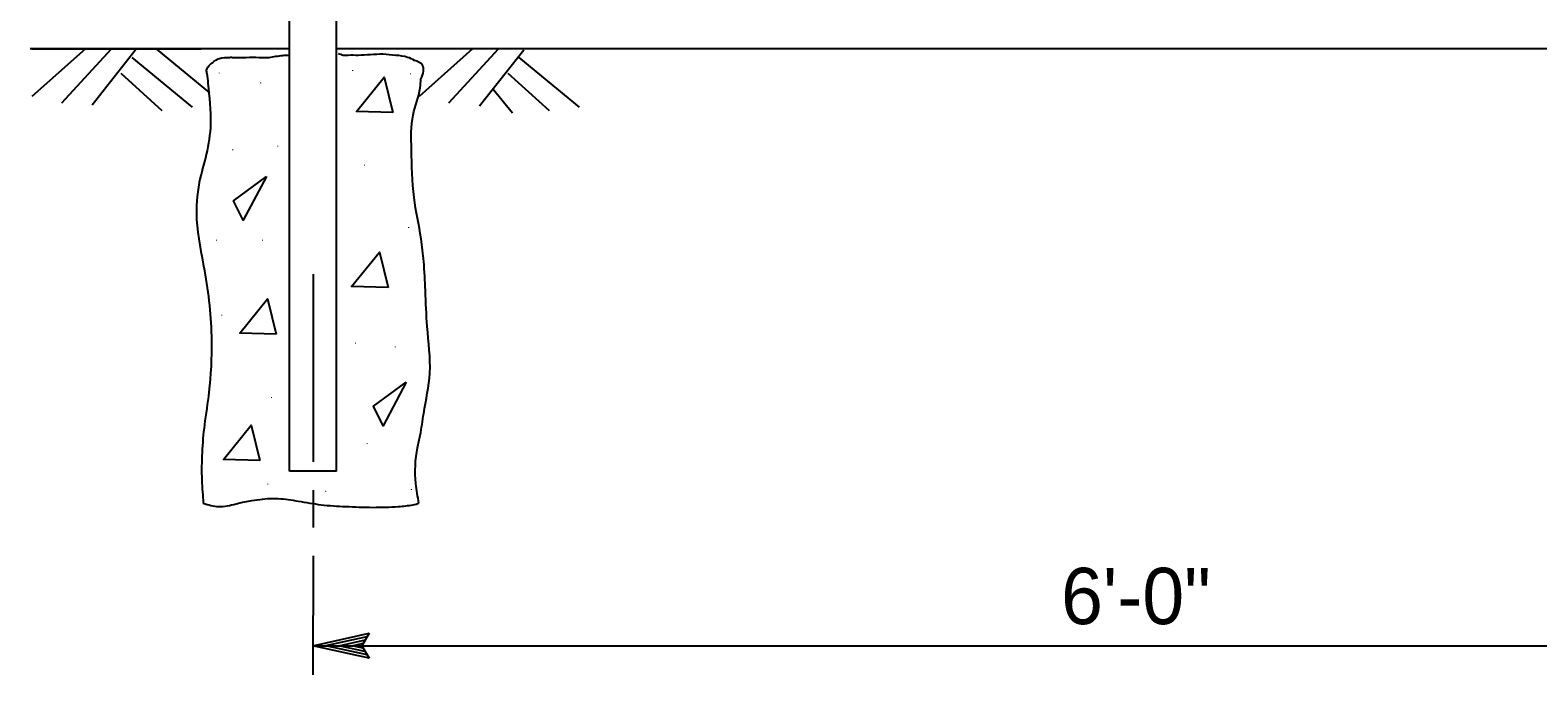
# Model space of a CAD drawing. Extents: x 6710407 to 6714861, y 1868090 to 1871317.
# Drawn here: x 6712140.6 to 6712301.4, y 1870303 to 1870371.8 of the extents above; entities that cross this region are included whole.
import ezdxf

# ---------------------------------------------------------------- set-up
doc = ezdxf.new("R2010")
doc.units = 0
for name, color, linetype in [('G-MARK', 7, 'Continuous'), ('G-TEXT', 7, 'Continuous'), ('Nongeo Data(60)', 7, 'Continuous')]:
    doc.layers.add(name, color=color, linetype=linetype)

msp = doc.modelspace()

# ---------------------------------------------------------------- linework, layer by layer
at = {"layer": 'G-MARK'}
msp.add_line((6712170.79, 1870306.15), (6712345.95, 1870306.15), dxfattribs=at)
for points in [[(6712170.83, 1870345.74), (6712170.81, 1870325.74)], [(6712170.81, 1870322.74), (6712170.81, 1870318.74)], [(6712170.8, 1870315.74), (6712170.79, 1870303.05)]]:
    msp.add_lwpolyline(points, dxfattribs=at)
at = {"layer": 'G-TEXT'}
for p, q in [((6712170.79, 1870306.15), (6712176.79, 1870307.48)), ((6712172.18, 1870306.16), (6712176.56, 1870307.13)), ((6712176.79, 1870307.48), (6712175.99, 1870306.15)), ((6712176.79, 1870307.48), (6712176.79, 1870307.48)), ((6712176.79, 1870304.81), (6712170.79, 1870306.15)), ((6712170.79, 1870306.15), (6712170.79, 1870306.15)), ((6712176.57, 1870305.17), (6712172.17, 1870306.15)), ((6712173.55, 1870306.15), (6712176.38, 1870306.78)), ((6712176.34, 1870305.53), (6712173.55, 1870306.15)), ((6712174.93, 1870306.15), (6712176.14, 1870306.42)), ((6712176.16, 1870305.88), (6712174.93, 1870306.15)), ((6712175.99, 1870306.15), (6712176.79, 1870304.81)), ((6712176.79, 1870304.81), (6712176.79, 1870304.81))]:
    msp.add_line(p, q, dxfattribs=at)
at = {"layer": 'Nongeo Data(60)'}
for p, q in [((6712168.3, 1870324.76), (6712168.3, 1870478.96)), ((6712173.3, 1870324.76), (6712173.3, 1870478.96)), ((6712168.3, 1870369.76), (6712140.63, 1870369.76)), ((6712146.52, 1870369.79), (6712140.82, 1870364.71)), ((6712140.82, 1870369.78), (6712158.88, 1870369.78)), ((6712149.26, 1870369.75), (6712143.97, 1870363.99)), ((6712151.93, 1870369.75), (6712147.23, 1870363.77)), ((6712154.12, 1870369.73), (6712159.76, 1870365.09)), ((6712343.3, 1870369.76), (6712173.3, 1870369.76)), ((6712187.81, 1870369.79), (6712182.11, 1870364.71)), ((6712190.55, 1870369.75), (6712185.26, 1870363.99)), ((6712193.27, 1870369.64), (6712188.57, 1870363.66)), ((6712151.47, 1870368.85), (6712157.91, 1870363.55)), ((6712192.76, 1870368.85), (6712199.2, 1870363.55)), ((6712150.29, 1870367.2), (6712154.69, 1870363.2)), ((6712191.58, 1870367.2), (6712195.98, 1870363.2)), ((6712190.02, 1870365.49), (6712192.08, 1870362.96)), ((6712173.3, 1870324.76), (6712168.3, 1870324.76))]:
    msp.add_line(p, q, dxfattribs=at)
msp.add_lwpolyline([(6712140.82, 1870369.78), (6712158.88, 1870369.78)], dxfattribs=at)
for points in [[(6712179.32, 1870363), (6712175.42, 1870363.11), (6712178.38, 1870366.77)], [(6712165.82, 1870356.16), (6712163.35, 1870351.51), (6712162.32, 1870353.59)], [(6712178.82, 1870344.33), (6712174.92, 1870344.43), (6712177.88, 1870348.09)], [(6712166.88, 1870339.35), (6712162.98, 1870339.46), (6712165.93, 1870343.12)], [(6712180.75, 1870334.26), (6712178.28, 1870329.6), (6712177.26, 1870331.68)], [(6712165.14, 1870325.9), (6712161.24, 1870326.01), (6712164.19, 1870329.67)]]:
    msp.add_lwpolyline(points, close=True, dxfattribs=at)
for points in [[(6712159.49, 1870367.16), (6712159.45, 1870367.5), (6712159.87, 1870368.13), (6712160.83, 1870368.76), (6712161.88, 1870368.87), (6712162.3, 1870368.87), (6712163.68, 1870368.87), (6712165.05, 1870368.87), (6712166.11, 1870368.87), (6712167.58, 1870369.08), (6712168.22, 1870369.08)], [(6712182.3, 1870366.55), (6712182.58, 1870367.39), (6712182.48, 1870368.02), (6712181.63, 1870368.55), (6712180.89, 1870368.87), (6712179.63, 1870369.08), (6712178.25, 1870369.19), (6712175.61, 1870369.08), (6712174.56, 1870369.08), (6712174.03, 1870369.08), (6712173.5, 1870369.29)], [(6712159.49, 1870367.16), (6712159.59, 1870366.09), (6712159.87, 1870361.78), (6712159.41, 1870358.51), (6712158.66, 1870355.51), (6712158.38, 1870351.58), (6712159.22, 1870346.16), (6712159.97, 1870338.68), (6712159.69, 1870333.16), (6712159.22, 1870329.69), (6712158.94, 1870323.8), (6712159.1, 1870321.34)], [(6712182.1, 1870321.34), (6712181.76, 1870323.43), (6712181.95, 1870327.26), (6712182.23, 1870328.57), (6712182.61, 1870330.91), (6712183.26, 1870335.21), (6712182.98, 1870340.17), (6712182.79, 1870344.01), (6712182.61, 1870347.09), (6712182.33, 1870349.53), (6712181.58, 1870353.92), (6712181.3, 1870359.07), (6712181.48, 1870362.72), (6712182.23, 1870365.62), (6712182.3, 1870366.55)], [(6712159.1, 1870321.34), (6712160.72, 1870320.99), (6712162.59, 1870321.27), (6712167.08, 1870321.84), (6712169.23, 1870321.56), (6712171.66, 1870321.18), (6712174.28, 1870320.99), (6712177.18, 1870320.9), (6712179.89, 1870320.99), (6712181.48, 1870321.18), (6712182.1, 1870321.34)]]:
    msp.add_spline(points, degree=3, dxfattribs=at)

# ---------------------------------------------------------------- texts
for p in [(6712160.74, 1870367.35), (6712174.98, 1870367.63), (6712181.14, 1870367.25), (6712165.16, 1870366.29), (6712162.18, 1870359.16), (6712166.99, 1870359.54), (6712176.23, 1870357.52), (6712180.95, 1870350.88), (6712160.45, 1870349.53), (6712165.36, 1870349.53), (6712161.02, 1870341.54), (6712175.27, 1870338.55), (6712179.51, 1870338.16), (6712166.32, 1870332.77), (6712176.52, 1870327.86), (6712165.93, 1870323.53), (6712172.09, 1870322.76), (6712181.24, 1870322.95)]:
    msp.add_text('.', height=0.8, rotation=266.9315, dxfattribs=at).set_placement(p)
msp.add_text('6\'-0"', height=6, dxfattribs=at).set_placement((6712250.59, 1870308.45))

doc.saveas('drawing.dxf')
